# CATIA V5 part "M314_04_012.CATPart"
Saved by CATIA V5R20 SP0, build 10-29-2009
Part number: M314_04_012
Source: Unknown
Property "ARTICLENO": "M314-04-012"
Property "B": "35.000"
Property "BOMINFO": "M314-04-012"
Property "CODE": "M314-04-012"
Property "D": "8.000"
Property "FINALFORCE": "78.4 (8)"
Property "INITIALFORCE": "19.6 (2)"
Property "K": "30.000"
Property "L": "125.000"
Property "LINA": "M314-04-012"
Property "M": "M16x2.0"
Property "NB": "M314-04-012"
Property "NBSYN": "$CODE."
Property "NN": "M314-04"
Property "NT": "Spring Plunger"
Property "SUPPLIER": "CF"
Property "SW": "5.000"
Bounding box of the stored display mesh (mm): x -8 to 8, y 0 to 155, z -8 to 8
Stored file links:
  C:\Users\Utente\Desktop\3D files M314\M314_04_012.CATPart
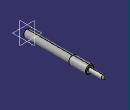
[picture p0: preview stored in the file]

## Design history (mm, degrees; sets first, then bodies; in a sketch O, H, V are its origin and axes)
Body1 "Geometry.1" (main body)
  Solid1 "M314_04_012.catpart": solid without history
